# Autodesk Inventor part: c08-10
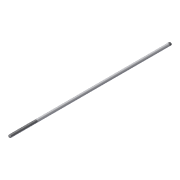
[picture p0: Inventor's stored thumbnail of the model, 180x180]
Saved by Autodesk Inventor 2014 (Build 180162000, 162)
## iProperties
Created: 2010-12
Part Number: c08-10
Material: Steel, High Strength Low Alloy
Document SubType Name: Modeling
Designer: Thom Tremblay
Mass: 1418.96 g
Surface Area: 459.995 cm^2
Volume: 180.99 cm^3
Density: 7.84 g/cm^3
Appearance: Semi-Polished
Author: Thom Tremblay
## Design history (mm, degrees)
sketch "Sketch1"
  geometry: C1 r 7.938 at (40.536, 0); 1 further point
  constraints: 1 centre point
  dimensions: "d0" = 15.875 diameter of C1
extrude "Extrusion1" new body sketch "Sketch1" distance "d1" = 914.4; taper "d2" = 0 deg
thread "Thread1" dims "d3" = 12.7, "d4" = 0
thread "Thread2" dims "d5" = 152.4, "d6" = 0
chamfer "Chamfer1" distance "d7" = 1.524; stored, may be unused: second distance "d8" = 3.175, angle "d9" = 45 deg
body "Solid1"
